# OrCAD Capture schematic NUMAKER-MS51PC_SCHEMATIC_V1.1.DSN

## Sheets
1 Nu-Link2-Me: size A3; title: Nu-Link2-Me; rev: 1.0; company: CMHuang; note: Nu-Link2-Me
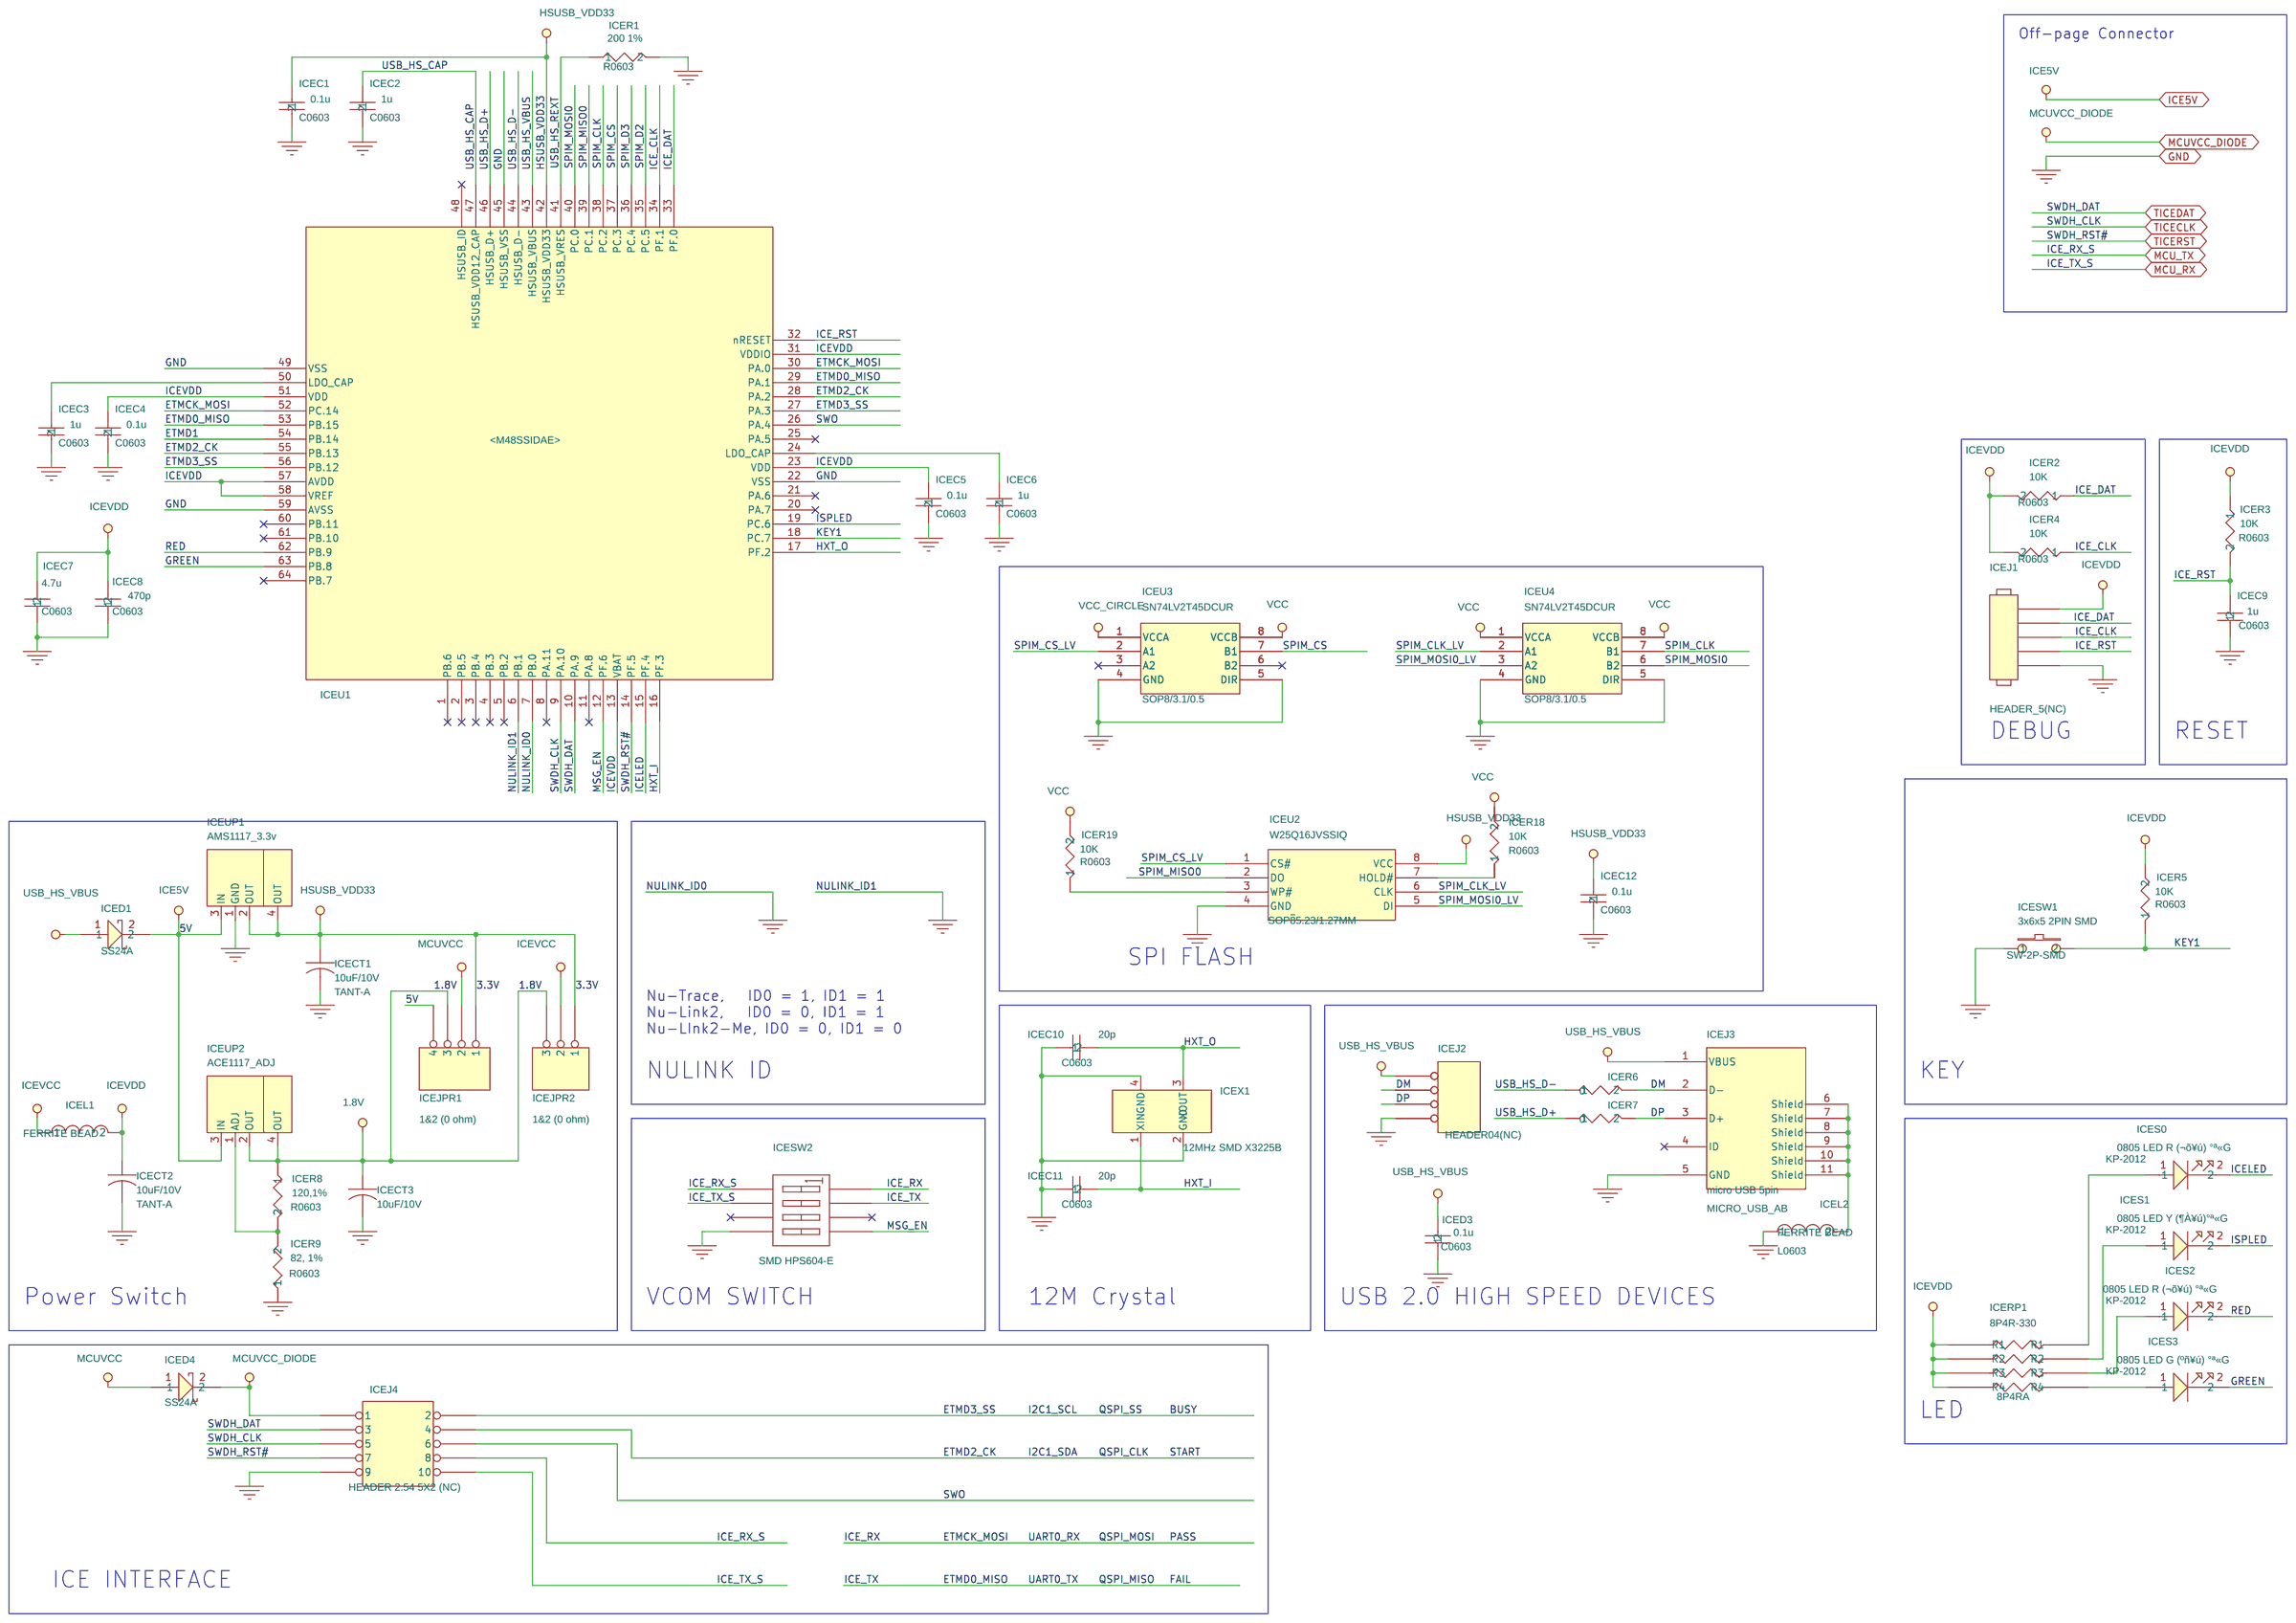
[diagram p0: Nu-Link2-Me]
2 MS51PC0AE: size Custom; title: MS51PC0AE; rev: v1.1; note: NuMaker-MS51PC
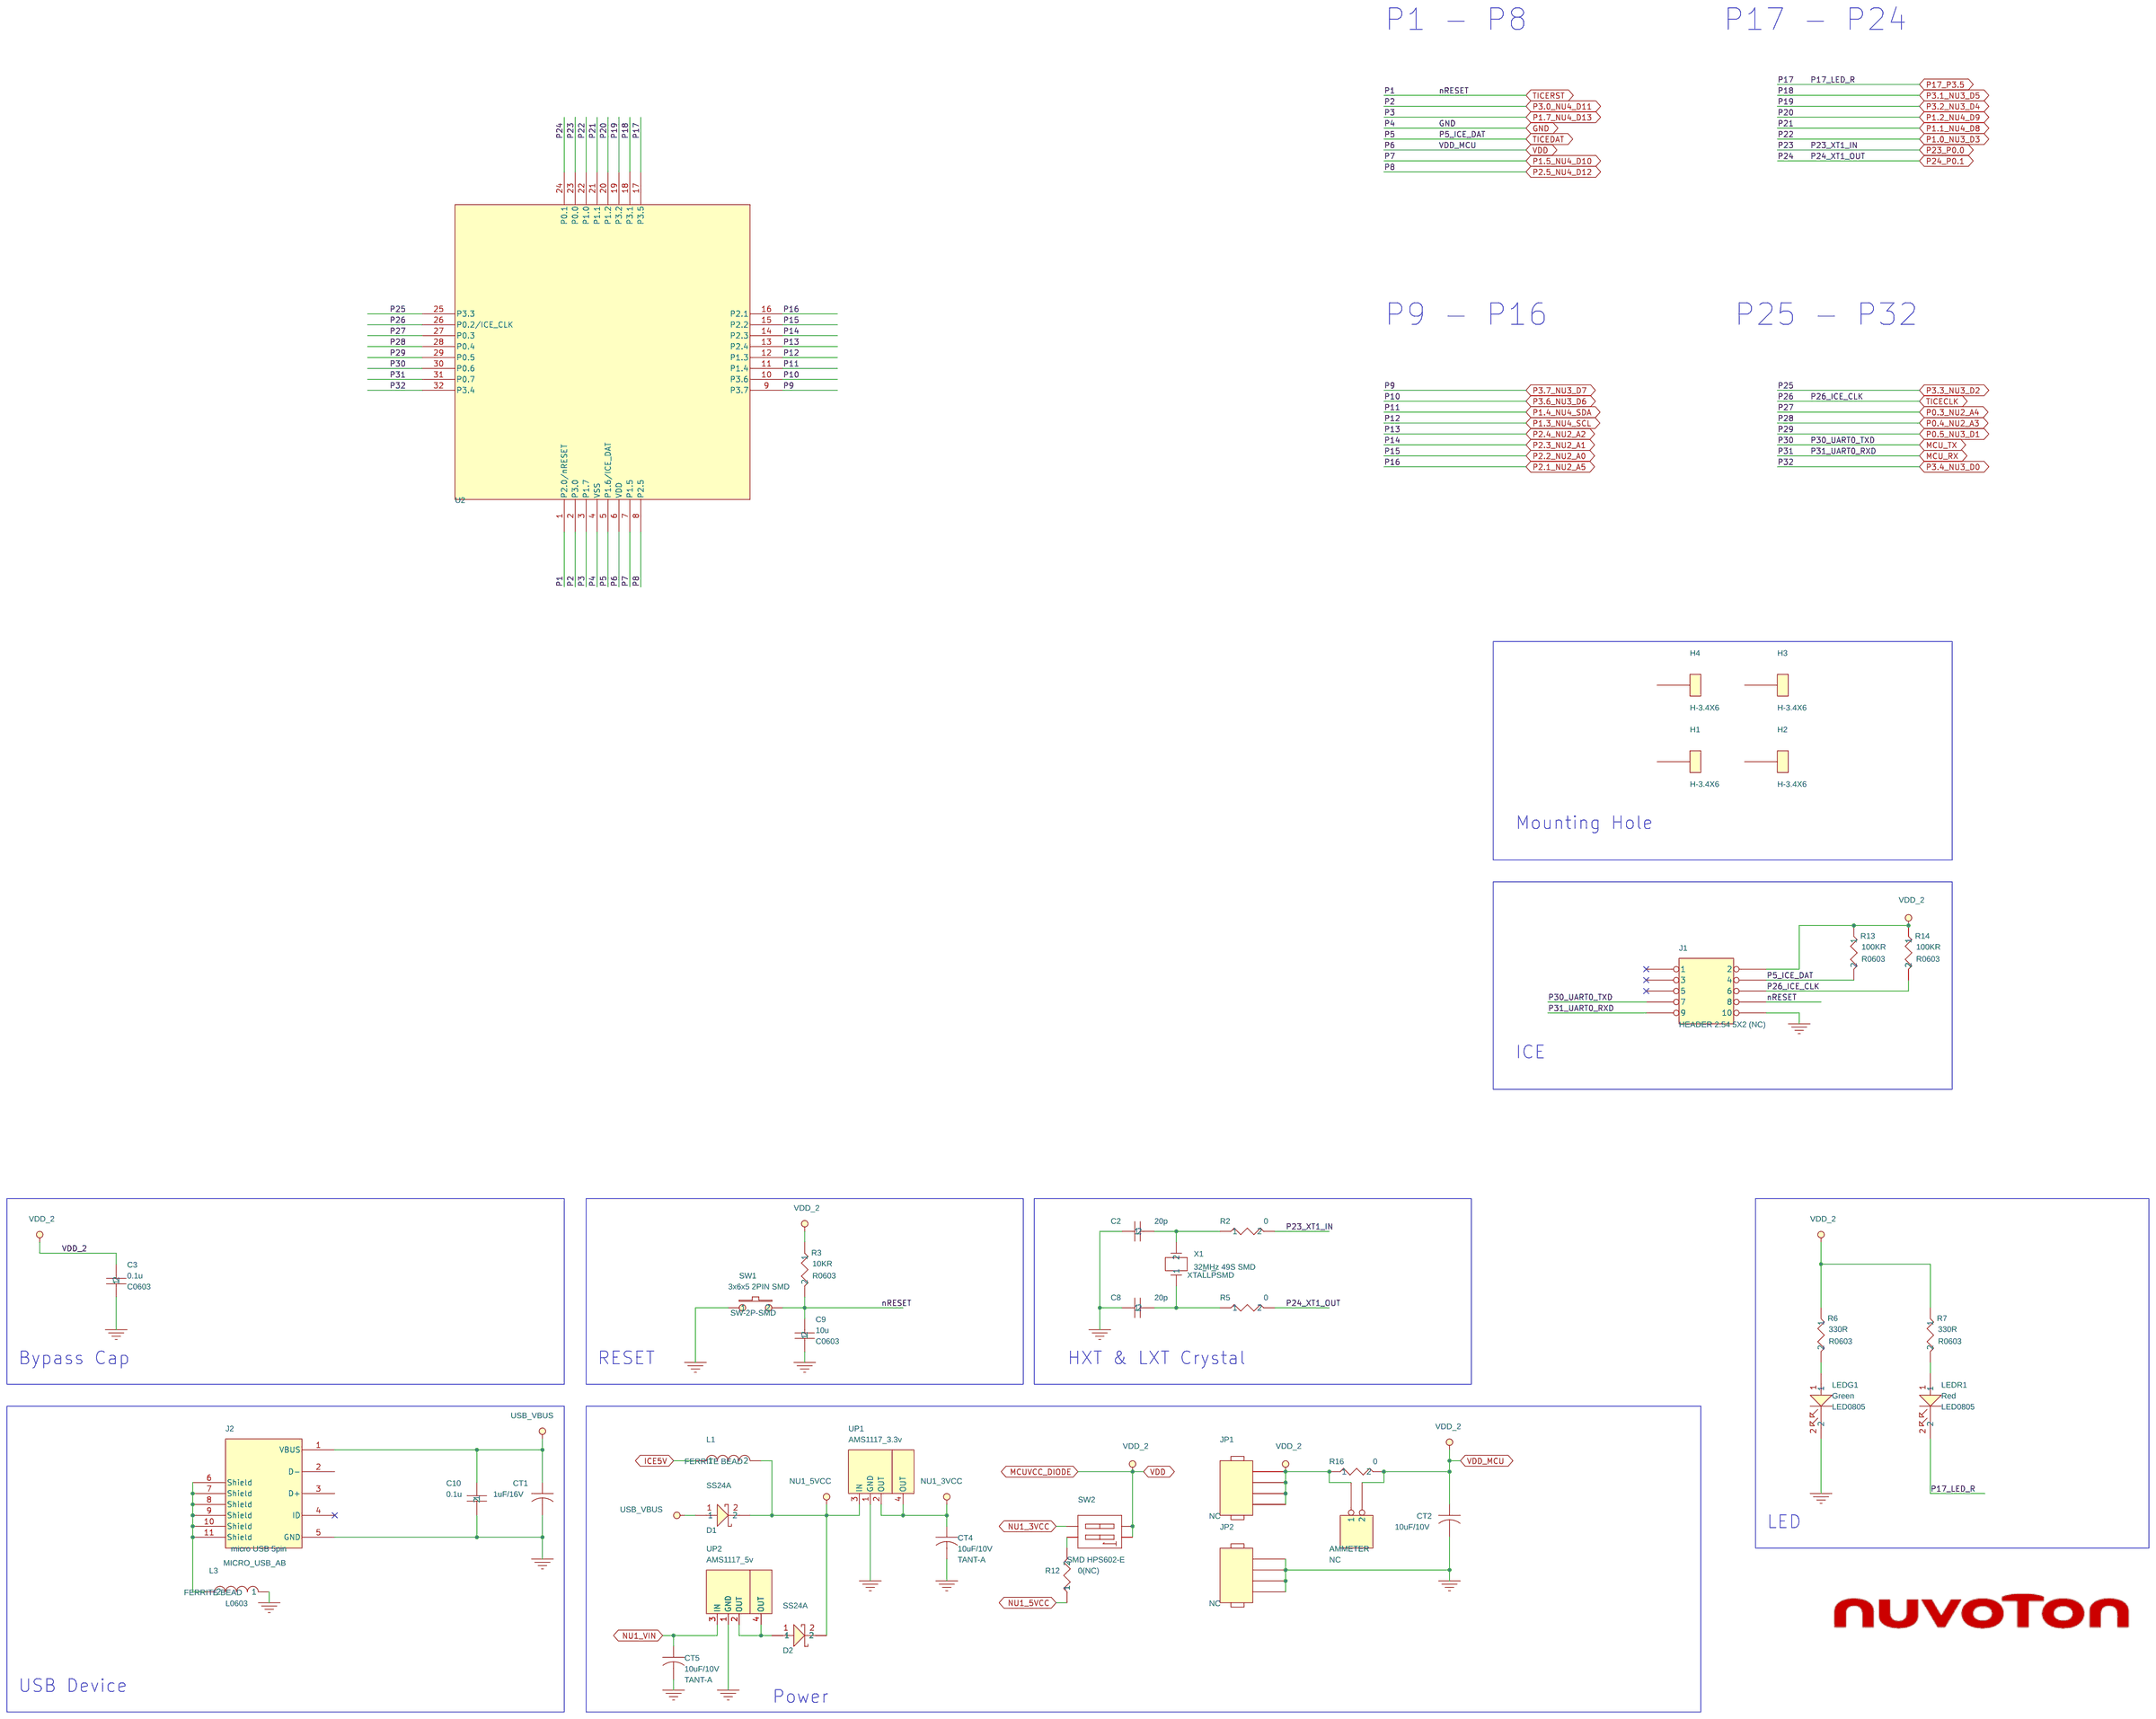
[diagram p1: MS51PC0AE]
3 Ext. Connector: size Custom; title: Ext. Connector; rev: v1.1; note: NuMaker-MS51PC
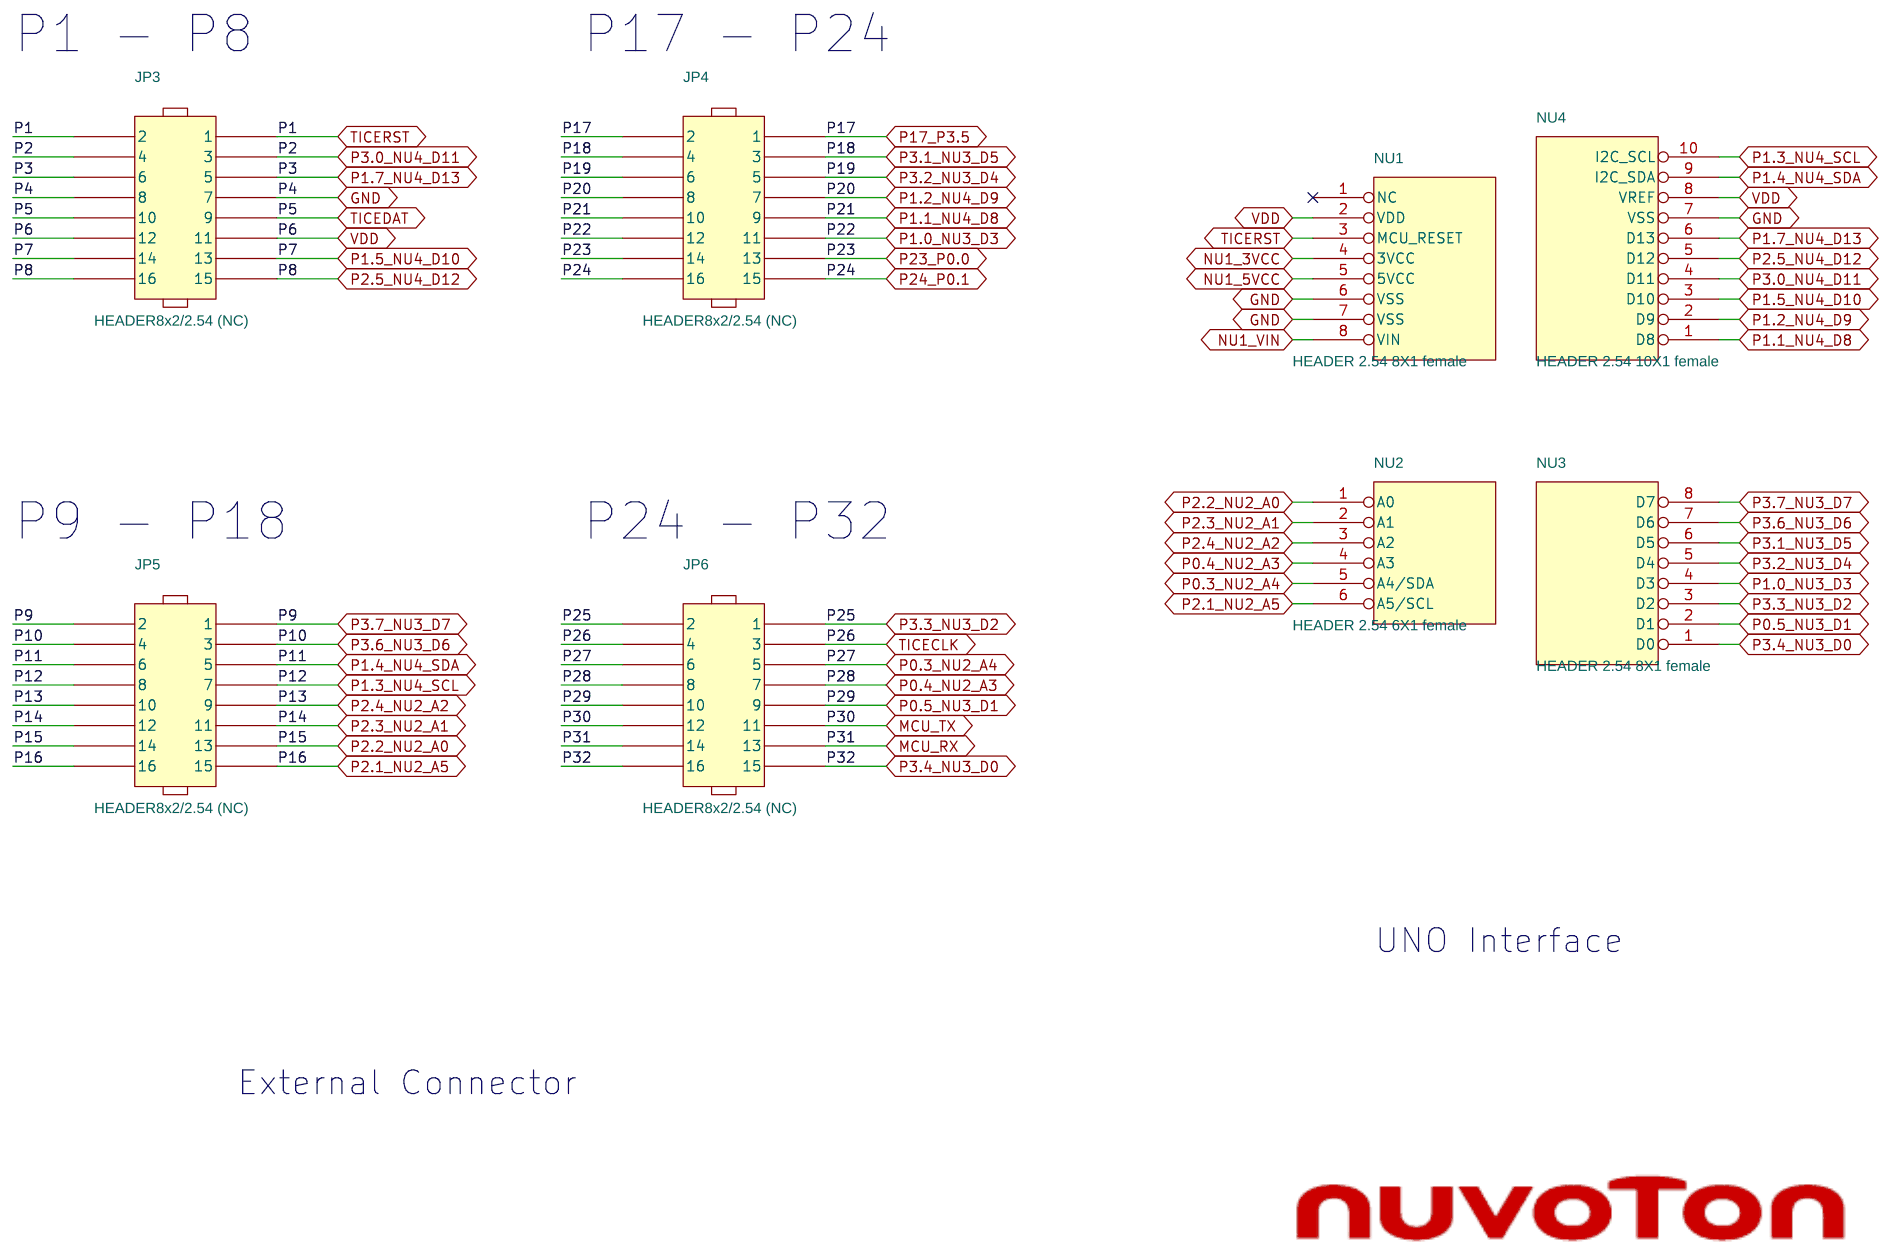
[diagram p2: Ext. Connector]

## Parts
sheet Ext. Connector
JP3  HEADER8x2/2.54 (NC)  [HEADER8x2/2.54(NC)]
JP4  HEADER8x2/2.54 (NC)  [HEADER8x2/2.54(NC)]
JP5  HEADER8x2/2.54 (NC)  [HEADER8x2/2.54(NC)]
JP6  HEADER8x2/2.54 (NC)  [HEADER8x2/2.54(NC)]
NU1  HEADER 2.54 8X1 female  [SIP-8P]
NU2  HEADER 2.54 6X1 female  [SIP-6P]
NU3  HEADER 2.54 8X1 female  [SIP-8P]
NU4  HEADER 2.54 10X1 female  [SIP-10P]
sheet MS51PC0AE
AMMETER  NC  [HEADER2X1]
C2  20p  [C0603]
C3  0.1u  [C0603]
C8  20p  [C0603]
C9  10u  [C0603]
C10  0.1u  [C0603]
CT1  1uF/16V  [TANT-A]
CT2  10uF/10V  [TANT-A]
CT4  10uF/10V  [TANT-A]
CT5  10uF/10V  [TANT-A]
D1  SS24A  [RB060L]
D2  SS24A  [RB060L]
H1  H-3.4X6  [H-3.4X6]
H2  H-3.4X6  [H-3.4X6]
H3  H-3.4X6  [H-3.4X6]
H4  H-3.4X6  [H-3.4X6]
J1  HEADER 2.54 5X2 (NC)  [HEADER5X2]
J2  micro USB 5pin  [MICRO_USB_AB]
JP1  NC  [header1x4]
JP2  NC  [header1x4]
L1  FERRITE BEAD  [L0603]
L3  FERRITE BEAD  [L0603]
LEDG1  Green  [LED0805]
LEDR1  Red  [LED0805]
R2  0  [R0603]
R3  10KR  [R0603]
R5  0  [R0603]
R6  330R  [R0603]
R7  330R  [R0603]
R12  0(NC)  [R0603]
R13  100KR  [R0603]
R14  100KR  [R0603]
R16  0  [R0603]
SW1  3x6x5 2PIN SMD  [SW-2P-SMD]
SW2  SMD HPS602-E  [SW1X2]
U2  MS51PC0AE  [MCU_LQFP_32_7X7]
UP1  AMS1117_3.3v  [SOT-223-1]
UP2  AMS1117_5v  [SOT-223-1]
X1  32MHz 49S SMD  [XTAL\LP\SMD]
sheet Nu-Link2-Me
ICEC1  0.1u  [C0603]
ICEC2  1u  [C0603]
ICEC3  1u  [C0603]
ICEC4  0.1u  [C0603]
ICEC5  0.1u  [C0603]
ICEC6  1u  [C0603]
ICEC7  4.7u  [C0603]
ICEC8  470p  [C0603]
ICEC9  1u  [C0603]
ICEC10  20p  [C0603]
ICEC11  20p  [C0603]
ICEC12  0.1u  [C0603]
ICECT1  10uF/10V  [TANT-A]
ICECT2  10uF/10V  [TANT-A]
ICECT3  10uF/10V  [TANT-A]
ICED1  SS24A  [RB060L]
ICED3  0.1u  [C0603]
ICED4  SS24A  [RB060L]
ICEJ1  HEADER_5(NC)  [HEADER5X1]
ICEJ2  HEADER04(NC)  [HEADER04]
ICEJ3  micro USB 5pin  [MICRO_USB_AB]
ICEJ4  HEADER 2.54 5X2 (NC)  [HEADER5X2]
ICEJPR1  1&2 (0 ohm)  [R0603X3]
ICEJPR2  1&2 (0 ohm)  [R0603X2]
ICEL1  FERRITE BEAD  [L0603]
ICEL2  FERRITE BEAD  [L0603]
ICER1  200 1%  [R0603]
ICER2  10K  [R0603]
ICER3  10K  [R0603]
ICER4  10K  [R0603]
ICER5  10K  [R0603]
ICER6  0  [R0603]
ICER7  0  [R0603]
ICER8  120,1%  [R0603]
ICER9  82, 1%  [R0603]
ICER18  10K  [R0603]
ICER19  10K  [R0603]
ICERP1  8P4R-330  [8P4RA]
ICES0  0805 LED R (¬õ¥ú) °ª«G  [KP-2012]
ICES1  0805 LED Y (¶À¥ú)°ª«G  [KP-2012]
ICES2  0805 LED R (¬õ¥ú) °ª«G  [KP-2012]
ICES3  0805 LED G (ºñ¥ú) °ª«G  [KP-2012]
ICESW1  3x6x5 2PIN SMD  [SW-2P-SMD]
ICESW2  SMD HPS604-E  [SW1X4]
ICEU1  M48SSIDAE  [LQFP64_7x7_M48SSIDAE]
ICEU2  W25Q16JVSSIQ  [SOP8\5.23/1.27MM]
ICEU3  SN74LV2T45DCUR  [SOP8/3.1/0.5]
ICEU4  SN74LV2T45DCUR  [SOP8/3.1/0.5]
ICEUP1  AMS1117_3.3v  [SOT-223-1]
ICEUP2  ACE1117_ADJ  [SOT-223-1]
ICEX1  12MHz SMD X3225B  [CRYSTAL_SMD]

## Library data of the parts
JP3 = HEADER_8X2_3
JP4 = HEADER_8X2_1
JP5 = HEADER_8X2
JP6 = HEADER_8X2_2
NU1 = POWER_CONNECT_0
NU2 = ADC_CONNECT_0
NU3 = PWM0_CONNECT_0
NU4 = PWM1_CONNECT_1
AMMETER = HEADER_2
C2 = C_20p
C3 = CAP-C: Package: 0603; element_no: C0004
C8 = C_20p_1
C9 = CAP-C_1: Package: 0603; element_no: C0006
C10 = C_0.1u: element_no: C0004
CT1 = C_1uF_16V
CT2 CT4 CT5 ICECT1-ICECT3 = C_10uF_10V
D1 ICED1 = D_SS24A
D2 ICED4 = D_SS24A_1
H1-H4 = TEST_POINT
ICEJ4 J1 = HEADER_5X2
ICEJ3 J2 = micro_USB_5pin_0
JP1 JP2 = HEADER_4
ICEL2 L1 = FERRITE_BEAD_1
ICEL1 L3 = FERRITE_BEAD
LEDG1 = LED_0_1: Package: KP-2012; Vendor: Kingbright
LEDR1 = LED_0: Package: KP-2012; Vendor: Kingbright
R2 = R_0_2
ICER8 R3 = R_0_3: Package: 0603
R5 = R_0_1
ICER18 R6 = R_0_6: Package: 0603
ICER2 R7 = R_0: Package: 0603
R12 = R_0_5
ICER3 R13 = R_0_4: Package: 0603
ICER4 R14 = R_0_7: Package: 0603
R16 = R_0_8
ICESW1 SW1 = SW_PUSHBUTTON_0
SW2 = SW_DIP-4_2
U2 = MS51PC0AE
ICEUP1 UP1 UP2 = TO-247_Regulator_10
X1 = Xtal_12MHz
ICEC1 = CAP-C_9: Package: 0603; element_no: C0004
ICEC2 = CAP-C_10: Package: 0603; element_no: C0006
ICEC3 = CAP-C_11: Package: 0603; element_no: C0006
ICEC4 = CAP-C_2: Package: 0603; element_no: C0004
ICEC5 = CAP-C_4: Package: 0603; element_no: C0004
ICEC6 = CAP-C_5: Package: 0603; element_no: C0006
ICEC7 = CAP-C: Package: 0603
ICEC8 = CAP-C_6: Package: 0603
ICEC9 = CAP-C_7: Package: 0603; element_no: C0006
ICEC10 = CAP-C_3: Package: 0603
ICEC11 = CAP-C_12: Package: 0603
ICEC12 = CAP-C_8: Package: 0603; element_no: C0004
ICED3 = CAP-C_1: Package: 0603; element_no: C0004
ICEJ1 = HEADER_5_v2
ICEJ2 = HEADER_4_v2
ICEJPR1 = HEADER_3_0
ICEJPR2 = HEADER_3
ICER1 = R_0_5: Package: 0603
ICER5 = R_0_2: Package: 0603
ICER6 = R_33
ICER7 = R_33_1
ICER9 = R_0_8: Package: 0603
ICER19 = R_0_1: Package: 0603
ICERP1 = R-PACK8_0
ICES0 = LED_0_3: Vendor: Kingbright
ICES1 = LED_0_1: Vendor: Kingbright
ICES2 = LED_0: Vendor: Kingbright
ICES3 = LED_0_2: Vendor: Kingbright
ICESW2 = SW_DIP-4_SM
ICEU1 = M487SIDAE_0: M487SIDAE: <M48SSIDAE>
ICEU2 = W25P10_20_40_SOIC_0: Package: SOP8; Vendor: WINBOND
ICEU3 ICEU4 = SN74LV2T45
ICEUP2 = TO-247_Regulator_0
ICEX1 = Crystal_SMD_1

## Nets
1.8V: ICECT3.1 ICEJPR1.3 ICEJPR2.3 ICER8.1 ICEUP2.2(OUT) ICEUP2.4(OUT)
3.3V: ICEC1.1 ICEC12.1 ICECT1.1 ICEJPR1.1 ICEJPR2.1 ICER18.2 ICER19.2 ICEU1.42(HSUSB_VDD33) ICEU2.8(VCC) ICEU3.1(VCCA) ICEU4.1(VCCA) ICEUP1.2(OUT) ICEUP1.4(OUT)
GND: C2.1 C3.1 C8.1 C9.1 C10.2 CT1.2 CT2.2 CT4.2 CT5.2 ICEC1.2 ICEC2.2 ICEC3.2 ICEC4.2 ICEC5.2 ICEC6.2 ICEC7.1 ICEC8.1 ICEC9.1 ICEC10.1 ICEC11.1 ICEC12.2 ICECT1.2 ICECT2.2 ICECT3.2 ICED3.1 ICEJ1.5 ICEJ2.4 ICEJ3.5(GND) ICEJ4.9 ICEL2.1 ICER1.2 ICER9.1 ICESW1.1 ICESW2.4(A4) ICEU1.6(PB.1) ICEU1.7(PB.0) ICEU1.22(VSS) ICEU1.45(HSUSB_VSS) ICEU1.49(VSS) ICEU1.59(AVSS) ICEU2.4(GND) ICEU3.4(GND) ICEU3.5(DIR) ICEU4.4(GND) ICEU4.5(DIR) ICEUP1.1(GND) ICEX1.2(GND) ICEX1.4(GND) J1.10 J2.5(GND) JP2.1 JP2.2 JP2.3 JP2.4 JP3.7 JP3.8 L3.1 LEDG1.2 NU1.6(VSS) NU1.7(VSS) NU4.7(VSS) SW1.1 U2.4(VSS) UP1.1(GND) UP2.1(GND)
VDD: AMMETER.1 AMMETER.2 C3.2 CT2.1 ICED4.2 ICEJ4.1 J1.2 JP1.1 JP1.2 JP1.3 JP1.4 JP3.11 JP3.12 NU1.2(VDD) NU4.8(VREF) R3.1 R6.1 R7.1 R13.1 R14.1 R16.1 R16.2 SW2.3(B1) SW2.4(B2) U2.6(VDD)
BUSY: ICEJ4.2 ICEU1.27(PA.3) ICEU1.56(PB.12)
DM: ICEJ2.2 ICEJ3.2(D-) ICER6.2
DP: ICEJ2.3 ICEJ3.3(D+) ICER7.2
ETMD1: ICEU1.54(PB.14)
ETMD2_CK: ICEJ4.4 ICEU1.28(PA.2) ICEU1.55(PB.13)
GREEN: ICES3.2 ICEU1.63(PB.8)
HXT_I: ICEC11.2 ICEU1.16(PF.3) ICEX1.1(XIN)
HXT_O: ICEC10.2 ICEU1.17(PF.2) ICEX1.3(XOUT)
ICE5V: ICED1.2 ICEJPR1.4 ICEUP1.3(IN) ICEUP2.3(IN) L1.1
ICE_CLK: ICEJ1.3 ICER4.1 ICEU1.34(PF.1)
ICE_DAT: ICEJ1.2 ICER2.1 ICEU1.33(PF.0)
ICE_RST: ICEC9.2 ICEJ1.4 ICER3.2 ICEU1.32(nRESET)
ICE_RX: ICESW2.8(B1) ICEU1.30(PA.0) ICEU1.52(PC.14)
ICE_TX: ICESW2.7(B2) ICEU1.29(PA.1) ICEU1.53(PB.15)
ICELED: ICES0.2 ICEU1.15(PF.4)
ICEVCC: ICEJPR2.2 ICEL1.1
ICEVDD: ICEC4.1 ICEC5.1 ICEC7.2 ICEC8.2 ICECT2.1 ICEJ1.1 ICEL1.2 ICER2.2 ICER3.1 ICER4.2 ICER5.2 ICERP1.1(R1) ICERP1.3(R2) ICERP1.5(R3) ICERP1.7(R4) ICEU1.13(VBAT) ICEU1.23(VDD) ICEU1.31(VDDIO) ICEU1.51(VDD) ICEU1.57(AVDD) ICEU1.58(VREF) ICEU3.8(VCCB) ICEU4.8(VCCB)
ISPLED: ICES1.2 ICEU1.19(PC.6)
KEY1: ICER5.1 ICESW1.2 ICEU1.18(PC.7)
MCU_RX: ICEJ4.10 ICESW2.2(A2) J1.9 JP6.13 JP6.14 U2.31(P0.7)
MCU_TX: ICEJ4.8 ICESW2.1(A1) J1.7 JP6.11 JP6.12 U2.30(P0.6)
MCUVCC: ICED4.1 ICEJPR1.2
MSG_EN: ICESW2.5(B4) ICEU1.12(PF.6)
NU1_3VCC: CT4.1 NU1.4(3VCC) SW2.2(A2) UP1.2(OUT) UP1.4(OUT)
NU1_5VCC: D1.2 D2.2 L1.2 NU1.5(5VCC) R12.1 UP1.3(IN)
NU1_VIN: CT5.1 NU1.8(VIN) UP2.3(IN)
P0.3_NU2_A4: JP6.5 JP6.6 NU2.5(A4/SDA) U2.27(P0.3)
P0.4_NU2_A3: JP6.7 JP6.8 NU2.4(A3) U2.28(P0.4)
P0.5_NU3_D1: JP6.9 JP6.10 NU3.2(D1) U2.29(P0.5)
P1.0_NU3_D3: JP4.11 JP4.12 NU3.4(D3) U2.22(P1.0)
P1.1_NU4_D8: JP4.9 JP4.10 NU4.1(D8) U2.21(P1.1)
P1.2_NU4_D9: JP4.7 JP4.8 NU4.2(D9) U2.20(P1.2)
P1.3_NU4_SCL: JP5.7 JP5.8 NU4.10(I2C_SCL) U2.12(P1.3)
P1.4_NU4_SDA: JP5.5 JP5.6 NU4.9(I2C_SDA) U2.11(P1.4)
P1.5_NU4_D10: JP3.13 JP3.14 NU4.3(D10) U2.7(P1.5)
P1.7_NU4_D13: JP3.5 JP3.6 NU4.6(D13) U2.3(P1.7)
P2.1_NU2_A5: JP5.15 JP5.16 NU2.6(A5/SCL) U2.16(P2.1)
P2.2_NU2_A0: JP5.13 JP5.14 NU2.1(A0) U2.15(P2.2)
P2.3_NU2_A1: JP5.11 JP5.12 NU2.2(A1) U2.14(P2.3)
P2.4_NU2_A2: JP5.9 JP5.10 NU2.3(A2) U2.13(P2.4)
P2.5_NU4_D12: JP3.15 JP3.16 NU4.5(D12) U2.8(P2.5)
P3.0_NU4_D11: JP3.3 JP3.4 NU4.4(D11) U2.2(P3.0)
P3.1_NU3_D5: JP4.3 JP4.4 NU3.6(D5) U2.18(P3.1)
P3.2_NU3_D4: JP4.5 JP4.6 NU3.5(D4) U2.19(P3.2)
P3.3_NU3_D2: JP6.1 JP6.2 NU3.3(D2) U2.25(P3.3)
P3.4_NU3_D0: JP6.15 JP6.16 NU3.1(D0) U2.32(P3.4)
P3.6_NU3_D6: JP5.3 JP5.4 NU3.7(D6) U2.10(P3.6)
P3.7_NU3_D7: JP5.1 JP5.2 NU3.8(D7) U2.9(P3.7)
P17_P3.5: JP4.1 JP4.2 LEDR1.2 U2.17(P3.5)
P23_P0.0: JP4.13 JP4.14 R2.2 U2.23(P0.0)
P24_P0.1: JP4.15 JP4.16 R5.2 U2.24(P0.1)
RED: ICES2.2 ICEU1.62(PB.9)
SPIM_CLK: ICEU1.38(PC.2) ICEU4.7(B1)
SPIM_CLK_LV: ICEU2.6(CLK) ICEU4.2(A1)
SPIM_CS: ICEU1.37(PC.3) ICEU3.7(B1)
SPIM_CS_LV: ICEU2.1(CS#) ICEU3.2(A1)
SPIM_D2: ICEU1.35(PC.5)
SPIM_D3: ICEU1.36(PC.4)
SPIM_MISO0: ICEU1.39(PC.1) ICEU2.2(DO)
SPIM_MOSI0: ICEU1.40(PC.0) ICEU4.6(B2)
SPIM_MOSI0_LV: ICEU2.5(DI) ICEU4.3(A2)
SWO: ICEJ4.6 ICEU1.26(PA.4)
TICECLK: ICEJ4.5 ICEU1.9(PA.10) J1.6 JP6.3 JP6.4 R14.2 U2.26(P0.2/ICE_CLK)
TICEDAT: ICEJ4.3 ICEU1.10(PA.9) J1.4 JP3.9 JP3.10 R13.2 U2.5(P1.6/ICE_DAT)
TICERST: C9.2 ICEJ4.7 ICEU1.14(PF.5) J1.8 JP3.1 JP3.2 NU1.3(MCU_RESET) R3.2 SW1.2 U2.1(P2.0/nRESET)
USB_HS_CAP: ICEC2.1 ICEU1.47(HSUSB_VDD12_CAP)
USB_HS_D+: ICER7.1 ICEU1.46(HSUSB_D+)
USB_HS_D-: ICER6.1 ICEU1.44(HSUSB_D-)
USB_HS_REXT: ICER1.1 ICEU1.41(HSUSB_VRES)
USB_HS_VBUS: ICED1.1 ICED3.2 ICEJ2.1 ICEJ3.1(VBUS) ICEU1.43(HSUSB_VBUS)
USB_VBUS: C10.1 CT1.1 D1.1 J2.1(VBUS)
N16825237: LEDG1.1 R6.2
N16825240: LEDR1.1 R7.2
N16840819: ICEC6.1 ICEU1.24(LDO_CAP)
N16840960: ICEC3.1 ICEU1.50(LDO_CAP)
N17019924: ICER8.2 ICER9.2 ICEUP2.1(ADJ)
N17029977: ICERP1.8(R4) ICES3.1
N17029979: ICERP1.6(R3) ICES2.1
N17030004: ICERP1.4(R2) ICES1.1
N17030010: ICERP1.2(R1) ICES0.1
N17042369: ICEJ3.6(Shield) ICEJ3.7(Shield) ICEJ3.8(Shield) ICEJ3.9(Shield) ICEJ3.10(Shield) ICEJ3.11(Shield) ICEL2.2
N17110356: J2.6(Shield) J2.7(Shield) J2.8(Shield) J2.9(Shield) J2.10(Shield) J2.11(Shield) L3.2
N17125028: R12.2 SW2.1(A1)
N17155328: ICER18.1 ICEU2.7(HOLD#)
N17155343: ICER19.1 ICEU2.3(WP#)
N17159369: C8.2 R5.1 X1.1
N17159371: C2.2 R2.1 X1.2
N17167442: D2.1 UP2.2(OUT) UP2.4(OUT)

Not connected (* = marked no-connect by the designer): H1 1; H2 1; H3 1; H4 1; ICEJ3 4(ID)*; ICESW2 3(A3)* 6(B3)*; ICEU1 1(PB.6)* 2(PB.5)* 3(PB.4)* 4(PB.3)* 5(PB.2)* 8(PA.11)* 11(PA.8)* 20(PA.7)* 21(PA.6)* 25(PA.5)* 48(HSUSB_ID)* 60(PB.11)* 61(PB.10)* 64(PB.7)*; ICEU3 3(A2)* 6(B2)*; J1 1* 3* 5*; J2 2(D-) 3(D+) 4(ID)*; NU1 1(NC)*

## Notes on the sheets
sheet 1
- Off-page Connector
- DEBUG
- RESET
- SPI FLASH
- Nu-Trace,   ID0 = 1, ID1 = 1
  Nu-Link2,   ID0 = 0, ID1 = 1
  Nu-LInk2-Me, ID0 = 0, ID1 = 0
- NULINK ID
- KEY
- Power Switch
- VCOM SWITCH
- 12M Crystal
- USB 2.0 HIGH SPEED DEVICES
- LED
- ICE INTERFACE
sheet 2
- P1 - P8
- P17 - P24
- P9 - P16
- P25 - P32
- Mounting Hole
- ICE
- Bypass Cap
- RESET
- HXT & LXT Crystal
- LED
- USB Device
- Power
sheet 3
- P1 - P8
- P17 - P24
- P9 - P18
- P24 - P32
- UNO Interface
- External Connector
